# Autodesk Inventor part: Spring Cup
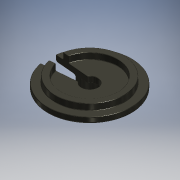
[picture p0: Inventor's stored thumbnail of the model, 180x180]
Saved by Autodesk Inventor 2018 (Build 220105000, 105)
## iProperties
Shininess: 50.0
Compacted: True
Length Units: 11272
Angle Units: 11279
Time Units: 11290
Mass Units: 11286
Length Display Precision: 4
Angle Display Precision: 2
Company: Autodesk
Created: 2000-03
Part Number: Spring Cup
Project: Inventor Samples
User Status: IN PROGRESS
Document SubType Name: Modeling
Designer: Autodesk, Inc.
Density: 1.13 g/cm^3
Mass: 0.4348 g
Surface Area: 6.80342 cm^2
Volume: 0.384779 cm^3
Material: Nylon-6/6
Appearance: Gunmetal
Density: 0.0
Volumn: 0.0
Area: 0.0
PropertySet Name: Model Information
Control State: 0
Master: False
Checked Out: False
Author: Autodesk, Inc.
Revision Number: A
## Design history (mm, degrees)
node "Revolution1" dims "d10" = 90 deg
  sketch "Sketch2"
    geometry: L1 (-6.24, 5.709)-(-6.24, -3.546); L2 (-9.224, -2.438)-(-9.224, 0.102); L3 (-9.224, 0.102)-(-7.891, 0.102); L4 (-7.891, 0.102)-(-7.891, 1.372); L5 (-7.891, 1.372)-(-11.955, 1.372); L6 (-11.955, 1.372)-(-11.955, 2.642); L7 (-11.955, 2.642)-(-13.225, 2.642); L8 (-13.225, 2.642)-(-13.225, 1.372); L9 (-13.225, 1.372)-(-14.812, 1.372); L10 (-14.812, 1.372)-(-14.812, 0.102); L11 (-14.812, 0.102)-(-10.494, 0.102); L12 (-10.494, 0.102)-(-10.494, -2.438); L13 (-10.494, -2.438)-(-9.224, -2.438)
    constraints: 26 end point, 10 parallel, 3 collinear, 1 perpendicular, 1 vertical, 1 other
    dimensions: "d0" = 13.97 diameter of L8 L1; "d1" = 1.27 distance of L6.end L7.end; "d2" = 1.27 distance from line of L7.end L9; "d3" = 2.54 distance between parallel lines of L13 L11; "d4" = 3.302 diameter of L4 L1; "d5" = 5.969 diameter of L2 L1; "d6" = 1.27 distance between parallel lines of L2 L12; "d7" = 17.145 diameter of L10 L1; "d8" = 11.43 diameter of L6 L1; "d9" = 1.27 distance between parallel lines of L9 L11
node "Fillet1" dims "d11" = 0.381
node "Extrusion1" dims "d15" = 25.4, "d16" = 0
  sketch "Sketch3"
    geometry: L1 (0, 0)-(-10.431, 0); L2 (-8.572, 1.544)-(-8.572, -1.544); L3 (-8.572, -1.544)-(0, -0.794); L4 (-8.572, 1.544)-(0, 0.794); L5 (0, 0.794)-(0, -0.794); C1 r 1.651 at (0, 0) reference; C2 r 5.715 at (0, 0) reference; C3 r 8.572 at (0, 0) reference
    constraints: 10 end point, 1 equal length, 1 horizontal, 1 midpoint, 1 perpendicular, 1 tangent, 1 vertical
    dimensions: "d12" = 10 deg angle of L3 L4; "d13" = 1.5875 distance of L4.end L3.end; "d14" = 0.79375 distance of C1.centre L3.end (= 0.5 x d13)
node "Fillet2" dims "d17" = 0.127
node "Fillet3" dims "d18" = 0.127
body "Solid1"
